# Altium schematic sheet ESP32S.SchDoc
size A4
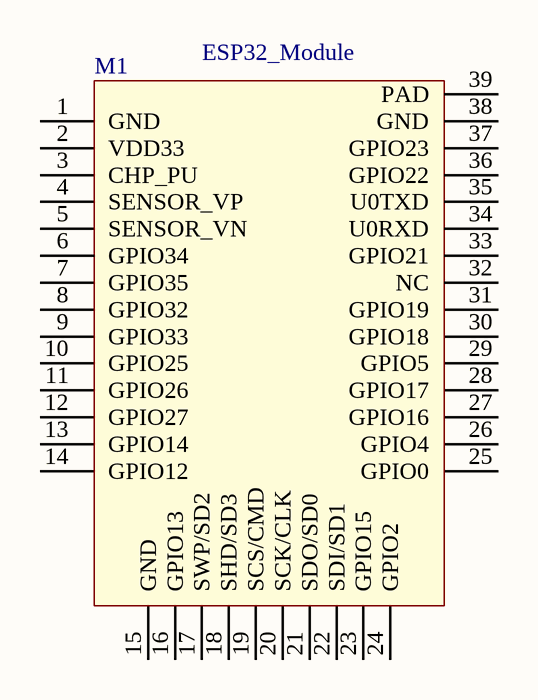
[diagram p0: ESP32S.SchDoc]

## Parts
M1  ESP32_Module  [ESP32_Module]

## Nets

Not connected (* = marked no-connect by the designer): M1 1(GND) 2(VDD33) 3(CHP_PU) 4(SENSOR_VP) 5(SENSOR_VN) 6(GPIO34) 7(GPIO35) 8(GPIO32) 9(GPIO33) 10(GPIO25) 11(GPIO26) 12(GPIO27) 13(GPIO14) 14(GPIO12) 15(GND) 16(GPIO13) 17(SWP/SD2) 18(SHD/SD3) 19(SCS/CMD) 20(SCK/CLK) 21(SDO/SD0) 22(SDI/SD1) 23(GPIO15) 24(GPIO2) 25(GPIO0) 26(GPIO4) 27(GPIO16) 28(GPIO17) 29(GPIO5) 30(GPIO18) 31(GPIO19) 32(NC) 33(GPIO21) 34(U0RXD) 35(U0TXD) 36(GPIO22) 37(GPIO23) 38(GND) 39(PAD)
